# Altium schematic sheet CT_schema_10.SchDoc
size 254 x 194 mm
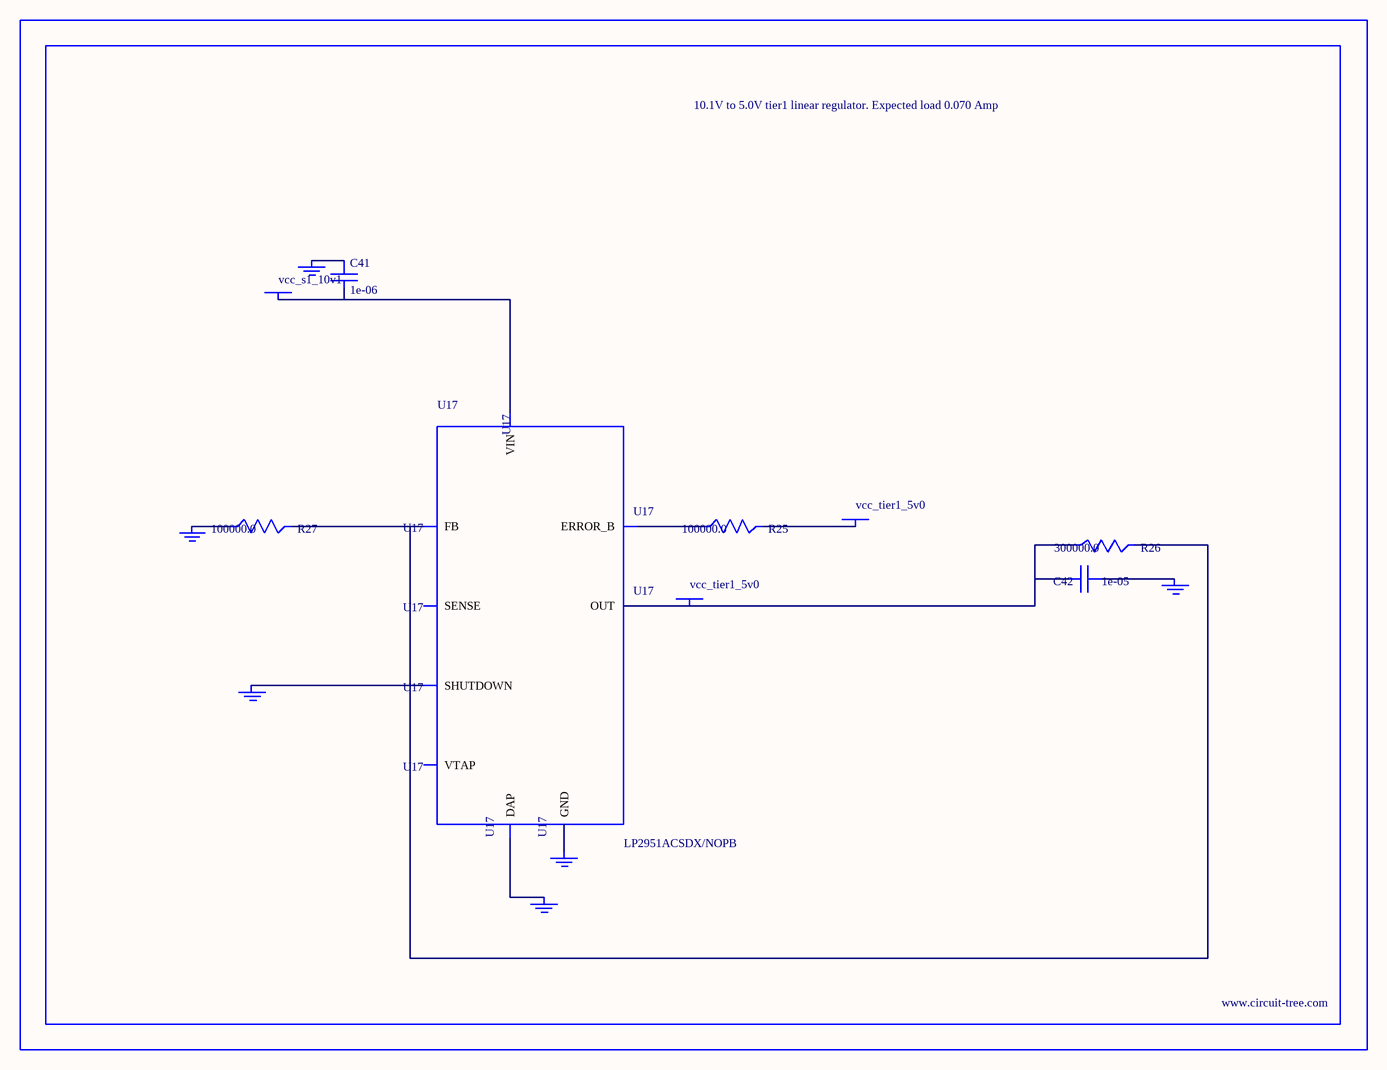
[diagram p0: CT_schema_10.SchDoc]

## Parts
BORDER9  (no value)
C41  1e-06  [C0603]
C42  1e-05  [C1210]
GND_INSTANCE_9_0  (no value)
GND_INSTANCE_9_1  (no value)
GND_INSTANCE_9_2  (no value)
GND_INSTANCE_9_3  (no value)
GND_INSTANCE_9_4  (no value)
GND_INSTANCE_9_5  (no value)
POWER_INSTANCE_9_0  vcc_tier1_5v0
POWER_INSTANCE_9_1  vcc_s1_10v1
POWER_INSTANCE_9_2  vcc_tier1_5v0
R25  100000.0  [R0603]
R26  300000.0  [R0603]
R27  100000.0  [R0603]
U17  LP2951ACSDX/NOPB  [WSON-8]

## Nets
NetC41_1: C41.1 GND_INSTANCE_9_3.0(GND)
NetC41_2: C41.2 POWER_INSTANCE_9_1.0(PWR) U17.8(VIN)
NetC42_1: C42.1 GND_INSTANCE_9_0.0(GND)
NetC42_2: C42.2 POWER_INSTANCE_9_2.0(PWR) R26.1 U17.1(OUT)
NetGND_INSTANCE_9_1_0: GND_INSTANCE_9_1.0(GND) U17.3(SHUTDOWN)
NetGND_INSTANCE_9_2_0: GND_INSTANCE_9_2.0(GND) R27.1
NetGND_INSTANCE_9_4_0: GND_INSTANCE_9_4.0(GND) U17.PAD(DAP)
NetGND_INSTANCE_9_5_0: GND_INSTANCE_9_5.0(GND) U17.4(GND)
NetPOWER_INSTANCE_9_0_0: POWER_INSTANCE_9_0.0(PWR) R25.2
NetR25_1: R25.1 U17.5(ERROR_B)
NetR26_2: R26.2 R27.2 U17.7(FB)

Not connected (* = marked no-connect by the designer): U17 2(SENSE) 6(VTAP)

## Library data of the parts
BORDER9 = BORDER_PAGE9
C41 = C0603C105K3RACTU
C42 = GRM32DR61E106MA12L
GND_INSTANCE_9_0-GND_INSTANCE_9_5 = GND
POWER_INSTANCE_9_0-POWER_INSTANCE_9_2 = PWR
R25 R27 = RC0603JR-07100KL
R26 = RC0603JR-07300KL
